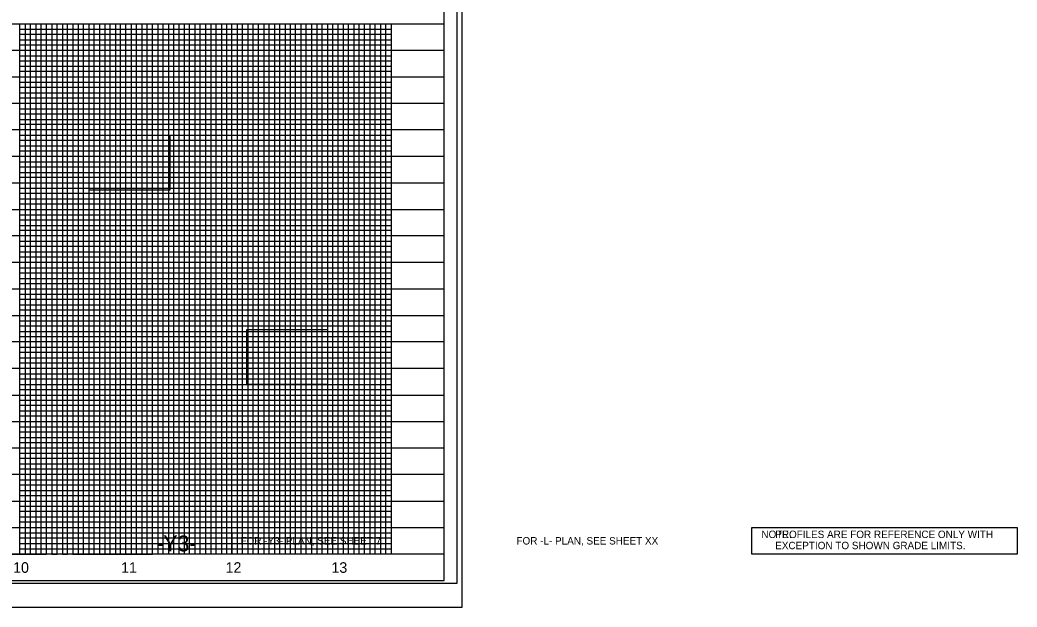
# Model space of a CAD drawing. Extents: x 1629737 to 1631945, y 1172886 to 1173986.
# Drawn here: x 1631004 to 1631945, y 1172886 to 1173440 of the extents above; entities that cross this region are included whole.
import ezdxf

# ---------------------------------------------------------------- set-up
doc = ezdxf.new("R2010")
doc.units = 0
for name, color, linetype in [('Exist Vertical Profile Horizontal Axis Label Major', 7, 'Continuous'), ('Prop Dimension Text', 7, 'Continuous'), ('Prop Grid Mask', 7, 'Continuous'), ('Sheet Data Field CELL', 7, 'Continuous'), ('Sheet Layout Profile Border Port 2', 7, 'Continuous'), ('Sheet Plot Border Inside CELL', 7, 'Continuous'), ('Sheet Plot Border Outside CELL', 7, 'Continuous'), ('Sheet Profile CELL', 7, 'Continuous'), ('Sheet Profile Grid Major CELL', 7, 'Continuous'), ('Sheet Profile Grid Middle CELL', 7, 'Continuous'), ('Sheet Profile Grid Minor CELL', 7, 'Continuous')]:
    doc.layers.add(name, color=color, linetype=linetype)

msp = doc.modelspace()

# ---------------------------------------------------------------- linework, layer by layer
at = {"layer": 'Prop Grid Mask'}
for points in [[(1631069.74, 1173330.94), (1631145.61, 1173330.94), (1631145.61, 1173279.17), (1631069.74, 1173279.17)], [(1631218.44, 1173147.7), (1631294.31, 1173147.7), (1631294.31, 1173095.94), (1631218.44, 1173095.94)], [(1631104.31, 1172955.94), (1631204.31, 1172955.94), (1631204.31, 1172935.94), (1631104.31, 1172935.94)], [(1631204.31, 1172960.94), (1631354.31, 1172960.94), (1631354.31, 1172935.94), (1631204.31, 1172935.94)]]:
    msp.add_lwpolyline(points, close=True, dxfattribs=at)
at = {"layer": 'Sheet Data Field CELL'}
msp.add_lwpolyline([(1631944.74, 1172935.94), (1631694.74, 1172935.94), (1631694.74, 1172960.94), (1631944.74, 1172960.94)], close=True, dxfattribs=at)
at = {"layer": 'Sheet Layout Profile Border Port 2'}
msp.add_lwpolyline([(1631004.31, 1173435.94), (1631354.31, 1173435.94), (1631354.31, 1172935.94), (1631204.31, 1172935.94), (1631129.31, 1172935.94), (1631004.31, 1172935.94)], close=True, dxfattribs=at)
at = {"layer": 'Sheet Plot Border Inside CELL'}
msp.add_lwpolyline([(1629750.31, 1172908.39), (1631416.81, 1172908.39), (1631416.81, 1173963.49), (1629750.31, 1173963.49)], close=True, dxfattribs=at)
at = {"layer": 'Sheet Plot Border Outside CELL'}
msp.add_lwpolyline([(1629737.31, 1172885.94), (1631421.31, 1172885.94), (1631421.31, 1173985.94), (1629737.31, 1173985.94)], close=True, dxfattribs=at)
at = {"layer": 'Sheet Profile CELL'}
for p, q in [((1629904.31, 1173435.94), (1631404.31, 1173435.94)), ((1631404.31, 1172935.94), (1629904.31, 1172935.94)), ((1629904.31, 1172910.94), (1631404.31, 1172910.94))]:
    msp.add_line(p, q, dxfattribs=at)
msp.add_lwpolyline([(1631404.31, 1173960.94), (1629904.31, 1173960.94), (1629904.31, 1172910.94), (1631404.31, 1172910.94)], close=True, dxfattribs=at)
at = {"layer": 'Sheet Profile Grid Major CELL'}
for p, q in [((1631004.31, 1173435.94), (1631054.31, 1173435.94)), ((1631004.31, 1172935.94), (1631004.31, 1173435.94)), ((1631004.31, 1173435.94), (1631054.31, 1173435.94)), ((1631054.31, 1173435.94), (1631054.31, 1172935.94)), ((1631104.31, 1173435.94), (1631154.31, 1173435.94)), ((1631104.31, 1172935.94), (1631104.31, 1173435.94)), ((1631104.31, 1173435.94), (1631154.31, 1173435.94)), ((1631154.31, 1173435.94), (1631154.31, 1172935.94)), ((1631204.31, 1173435.94), (1631254.31, 1173435.94)), ((1631304.31, 1173435.94), (1631354.31, 1173435.94)), ((1631304.31, 1173435.94), (1631354.31, 1173435.94)), ((1631304.31, 1172935.94), (1631304.31, 1173435.94)), ((1631354.31, 1173435.94), (1631354.31, 1172935.94)), ((1630954.31, 1172935.94), (1631004.31, 1172935.94)), ((1631054.31, 1172935.94), (1631104.31, 1172935.94))]:
    msp.add_line(p, q, dxfattribs=at)
for points in [[(1631204.31, 1172935.94), (1631204.31, 1173435.94), (1631254.31, 1173435.94), (1631254.31, 1172935.94)], [(1631404.31, 1173410.94), (1629904.31, 1173410.94)], [(1631404.31, 1173360.94), (1629904.31, 1173360.94)], [(1631404.31, 1173310.94), (1629904.31, 1173310.94), (1629904.31, 1173260.94), (1631404.31, 1173260.94)], [(1631404.31, 1173210.94), (1629904.31, 1173210.94), (1629904.31, 1173160.94), (1631404.31, 1173160.94)], [(1631404.31, 1173110.94), (1629904.31, 1173110.94), (1629904.31, 1173060.94), (1631404.31, 1173060.94)], [(1631404.31, 1173010.94), (1629904.31, 1173010.94), (1629904.31, 1173010.94), (1629904.31, 1172960.94), (1631404.31, 1172960.94)], [(1631404.31, 1172935.94), (1629904.31, 1172935.94)]]:
    msp.add_lwpolyline(points, dxfattribs=at)
at = {"layer": 'Sheet Profile Grid Middle CELL'}
for p, q in [((1631029.31, 1172935.94), (1631029.31, 1173435.94)), ((1631029.31, 1173435.94), (1631079.31, 1173435.94)), ((1631079.31, 1173435.94), (1631079.31, 1172935.94)), ((1630979.31, 1172935.94), (1631029.31, 1172935.94)), ((1631079.31, 1172935.94), (1631129.31, 1172935.94))]:
    msp.add_line(p, q, dxfattribs=at)
for points in [[(1631129.31, 1172935.94), (1631129.31, 1173435.94), (1631179.31, 1173435.94), (1631179.31, 1172935.94)], [(1631229.31, 1172935.94), (1631229.31, 1173435.94), (1631279.31, 1173435.94), (1631279.31, 1172935.94)], [(1631329.31, 1172935.94), (1631329.31, 1173435.94)], [(1629904.31, 1173385.94), (1631404.31, 1173385.94)], [(1631404.31, 1173335.94), (1629904.31, 1173335.94), (1629904.31, 1173285.94), (1631404.31, 1173285.94)], [(1631404.31, 1173235.94), (1629904.31, 1173235.94), (1629904.31, 1173185.94), (1631404.31, 1173185.94)], [(1631404.31, 1173135.94), (1629904.31, 1173135.94), (1629904.31, 1173085.94), (1631404.31, 1173085.94)], [(1631404.31, 1173035.94), (1629904.31, 1173035.94), (1629904.31, 1172985.94), (1631404.31, 1172985.94)], [(1631404.31, 1172935.94), (1629904.31, 1172935.94)]]:
    msp.add_lwpolyline(points, dxfattribs=at)
at = {"layer": 'Sheet Profile Grid Minor CELL'}
for p, q in [((1630999.31, 1173435.94), (1631009.31, 1173435.94)), ((1631009.31, 1173435.94), (1631009.31, 1172935.94)), ((1631014.31, 1172935.94), (1631014.31, 1173435.94)), ((1631014.31, 1173435.94), (1631019.31, 1173435.94)), ((1631019.31, 1173435.94), (1631019.31, 1172935.94)), ((1631024.31, 1172935.94), (1631024.31, 1173435.94)), ((1631024.31, 1173435.94), (1631034.31, 1173435.94)), ((1631034.31, 1173435.94), (1631034.31, 1172935.94)), ((1631039.31, 1172935.94), (1631039.31, 1173435.94)), ((1631039.31, 1173435.94), (1631044.31, 1173435.94)), ((1631044.31, 1173435.94), (1631044.31, 1172935.94)), ((1631049.31, 1172935.94), (1631049.31, 1173435.94)), ((1631049.31, 1173435.94), (1631059.31, 1173435.94)), ((1631059.31, 1173435.94), (1631059.31, 1172935.94)), ((1631064.31, 1172935.94), (1631064.31, 1173435.94)), ((1631064.31, 1173435.94), (1631069.31, 1173435.94)), ((1631069.31, 1173435.94), (1631069.31, 1172935.94)), ((1631074.31, 1172935.94), (1631074.31, 1173435.94)), ((1631074.31, 1173435.94), (1631084.31, 1173435.94)), ((1631084.31, 1173435.94), (1631084.31, 1172935.94)), ((1631089.31, 1172935.94), (1631089.31, 1173435.94)), ((1631089.31, 1173435.94), (1631094.31, 1173435.94)), ((1631094.31, 1173435.94), (1631094.31, 1172935.94)), ((1631004.31, 1173430.94), (1631354.31, 1173430.94)), ((1631354.31, 1173425.94), (1631004.31, 1173425.94)), ((1631004.31, 1173420.94), (1631354.31, 1173420.94)), ((1631354.31, 1173415.94), (1631004.31, 1173415.94)), ((1631004.31, 1173405.94), (1631354.31, 1173405.94)), ((1631354.31, 1173400.94), (1631004.31, 1173400.94)), ((1631004.31, 1173395.94), (1631354.31, 1173395.94)), ((1631354.31, 1173390.94), (1631004.31, 1173390.94)), ((1631004.31, 1173380.94), (1631354.31, 1173380.94)), ((1631354.31, 1173375.94), (1631004.31, 1173375.94)), ((1631004.31, 1173370.94), (1631354.31, 1173370.94)), ((1631354.31, 1173365.94), (1631004.31, 1173365.94)), ((1631004.31, 1173355.94), (1631354.31, 1173355.94)), ((1631354.31, 1173350.94), (1631004.31, 1173350.94)), ((1631004.31, 1173345.94), (1631354.31, 1173345.94)), ((1631354.31, 1173340.94), (1631004.31, 1173340.94)), ((1631004.31, 1173330.94), (1631354.31, 1173330.94)), ((1631354.31, 1173325.94), (1631004.31, 1173325.94)), ((1631004.31, 1173320.94), (1631354.31, 1173320.94)), ((1631354.31, 1173315.94), (1631004.31, 1173315.94)), ((1631004.31, 1173305.94), (1631354.31, 1173305.94)), ((1631354.31, 1173300.94), (1631004.31, 1173300.94)), ((1631004.31, 1173295.94), (1631354.31, 1173295.94)), ((1631354.31, 1173290.94), (1631004.31, 1173290.94)), ((1631004.31, 1173280.94), (1631354.31, 1173280.94)), ((1631354.31, 1173275.94), (1631004.31, 1173275.94)), ((1631004.31, 1173270.94), (1631354.31, 1173270.94)), ((1631354.31, 1173265.94), (1631004.31, 1173265.94)), ((1631004.31, 1173255.94), (1631354.31, 1173255.94)), ((1631354.31, 1173250.94), (1631004.31, 1173250.94)), ((1631004.31, 1173245.94), (1631354.31, 1173245.94)), ((1631354.31, 1173240.94), (1631004.31, 1173240.98)), ((1631004.31, 1173230.94), (1631354.31, 1173230.94)), ((1631354.31, 1173225.94), (1631004.31, 1173225.94)), ((1631004.31, 1173220.94), (1631354.31, 1173220.94)), ((1631354.31, 1173215.94), (1631004.31, 1173215.94)), ((1631004.31, 1173205.94), (1631354.31, 1173205.94)), ((1631354.31, 1173200.94), (1631004.31, 1173200.94)), ((1631004.31, 1173195.94), (1631354.31, 1173195.94)), ((1631354.31, 1173190.94), (1631004.31, 1173190.94)), ((1631004.31, 1173180.94), (1631354.31, 1173180.94)), ((1631354.31, 1173175.94), (1631004.31, 1173175.94)), ((1631004.31, 1173170.94), (1631354.31, 1173170.94)), ((1631354.31, 1173165.94), (1631004.31, 1173165.94)), ((1631004.31, 1173155.94), (1631354.31, 1173155.94)), ((1631354.31, 1173150.94), (1631004.31, 1173150.94)), ((1631004.31, 1173145.94), (1631354.31, 1173145.94)), ((1631354.31, 1173140.94), (1631004.31, 1173140.94)), ((1631004.31, 1173130.94), (1631354.31, 1173130.94)), ((1631354.31, 1173125.94), (1631004.31, 1173125.94)), ((1631004.31, 1173120.94), (1631354.31, 1173120.94)), ((1631354.31, 1173115.94), (1631004.31, 1173115.94)), ((1631004.31, 1173105.94), (1631354.31, 1173105.94)), ((1631354.31, 1173100.94), (1631004.31, 1173100.94)), ((1631004.31, 1173095.94), (1631354.31, 1173095.94)), ((1631354.31, 1173090.94), (1631004.31, 1173090.94)), ((1631004.31, 1173080.94), (1631354.31, 1173080.94)), ((1631354.31, 1173075.94), (1631004.31, 1173075.94)), ((1631004.31, 1173070.94), (1631354.31, 1173070.94)), ((1631354.31, 1173065.94), (1631004.31, 1173065.94)), ((1631004.31, 1173055.94), (1631354.31, 1173055.94)), ((1631354.31, 1173050.94), (1631004.31, 1173050.94)), ((1631004.31, 1173045.94), (1631354.31, 1173045.94)), ((1631354.31, 1173040.94), (1631004.31, 1173040.94)), ((1631004.31, 1173030.94), (1631354.31, 1173030.94)), ((1631354.31, 1173025.94), (1631004.31, 1173025.94)), ((1631004.31, 1173020.94), (1631354.31, 1173020.94)), ((1631354.31, 1173015.94), (1631004.31, 1173015.94)), ((1631004.31, 1173005.94), (1631354.31, 1173005.94)), ((1631354.31, 1173000.94), (1631004.31, 1173000.94)), ((1631004.31, 1172995.94), (1631354.31, 1172995.94)), ((1631354.31, 1172990.94), (1631004.31, 1172990.94)), ((1631004.31, 1172980.94), (1631354.31, 1172980.94)), ((1631354.31, 1172975.94), (1631004.31, 1172975.94)), ((1631004.31, 1172970.94), (1631354.31, 1172970.94)), ((1631354.31, 1172965.94), (1631004.31, 1172965.94)), ((1631004.31, 1172955.94), (1631354.31, 1172955.94)), ((1631354.31, 1172950.94), (1631004.31, 1172950.94)), ((1631004.31, 1172945.94), (1631354.31, 1172945.94)), ((1631004.31, 1172940.94), (1631354.31, 1172940.94)), ((1631009.31, 1172935.94), (1631014.31, 1172935.94)), ((1631019.31, 1172935.94), (1631024.31, 1172935.94)), ((1631034.31, 1172935.94), (1631039.31, 1172935.94)), ((1631044.31, 1172935.94), (1631049.31, 1172935.94)), ((1631059.31, 1172935.94), (1631064.31, 1172935.94)), ((1631069.31, 1172935.94), (1631074.31, 1172935.94)), ((1631084.31, 1172935.94), (1631089.31, 1172935.94))]:
    msp.add_line(p, q, dxfattribs=at)
for points in [[(1631094.31, 1172935.94), (1631099.31, 1172935.94), (1631099.31, 1173435.94), (1631109.31, 1173435.94), (1631109.31, 1172935.94)], [(1631114.31, 1172935.94), (1631114.31, 1173435.94), (1631119.31, 1173435.94), (1631119.31, 1172935.94)], [(1631124.31, 1172935.94), (1631124.31, 1173435.94), (1631134.31, 1173435.94), (1631134.31, 1172935.94)], [(1631139.31, 1172935.94), (1631139.31, 1173435.94), (1631144.31, 1173435.94), (1631144.31, 1172935.94)], [(1631149.31, 1172935.94), (1631149.31, 1173435.94), (1631159.31, 1173435.94), (1631159.31, 1172935.94)], [(1631164.31, 1172935.94), (1631164.31, 1173435.94), (1631169.31, 1173435.94), (1631169.31, 1172935.94)], [(1631174.31, 1172935.94), (1631174.31, 1173435.94), (1631184.31, 1173435.94), (1631184.31, 1172935.94)], [(1631189.31, 1172935.94), (1631189.31, 1173435.94), (1631194.31, 1173435.94), (1631194.31, 1172935.94)], [(1631199.31, 1172935.94), (1631199.31, 1173435.94), (1631209.31, 1173435.94), (1631209.31, 1172935.94)], [(1631214.31, 1172935.94), (1631214.31, 1173435.94), (1631219.31, 1173435.94), (1631219.31, 1172935.94)], [(1631224.31, 1172935.94), (1631224.31, 1173435.94), (1631234.31, 1173435.94), (1631234.31, 1172935.94)], [(1631239.31, 1172935.94), (1631239.31, 1173435.94), (1631244.31, 1173435.94), (1631244.31, 1172935.94)], [(1631249.31, 1172935.94), (1631249.31, 1173435.94), (1631259.31, 1173435.94), (1631259.31, 1172935.94)], [(1631264.31, 1172935.94), (1631264.31, 1173435.94), (1631269.31, 1173435.94), (1631269.31, 1172935.94)], [(1631274.31, 1172935.94), (1631274.31, 1173435.94), (1631284.31, 1173435.94), (1631284.31, 1172935.94)], [(1631289.31, 1172935.94), (1631289.31, 1173435.94), (1631294.31, 1173435.94), (1631294.31, 1172935.94)], [(1631299.31, 1172935.94), (1631299.31, 1173435.94), (1631309.31, 1173435.94), (1631309.31, 1172935.94)], [(1631314.31, 1172935.94), (1631314.31, 1173435.94), (1631319.31, 1173435.94), (1631319.31, 1172935.94)], [(1631324.31, 1172935.94), (1631324.31, 1173435.94), (1631334.31, 1173435.94), (1631334.31, 1172935.94)], [(1631339.31, 1172935.94), (1631339.31, 1173435.94), (1631344.31, 1173435.94), (1631344.31, 1172935.94)], [(1631349.31, 1172935.94), (1631349.31, 1173435.94), (1631354.31, 1173435.94)]]:
    msp.add_lwpolyline(points, dxfattribs=at)

# ---------------------------------------------------------------- texts
at = {"layer": 'Exist Vertical Profile Horizontal Axis Label Major'}
for s, p in [('10', (1630997.9, 1172918.23)), ('11', (1631099.74, 1172918.23)), ('12', (1631198.29, 1172918.23)), ('13', (1631298.12, 1172918.23))]:
    msp.add_text(s, height=10, dxfattribs=at).set_placement(p)
at = {"layer": 'Prop Dimension Text'}
msp.add_text('FOR -L- PLAN, SEE SHEET XX', height=7, rotation=360, dxfattribs=at).set_placement((1631472.6, 1172944.94))
at = {"layer": 'Sheet Data Field CELL'}
for s, p in [('NOTE: ', (1631703.64, 1172951.02)), ('     PROFILES ARE FOR REFERENCE ONLY WITH', (1631703.64, 1172951.02)), ('     EXCEPTION TO SHOWN GRADE LIMITS.', (1631703.64, 1172940.52))]:
    msp.add_text(s, height=7, dxfattribs=at).set_placement(p)
for s, height, p in [('-Y3-', 15, (1631132.88, 1172938.44)), ('FOR -Y3- PLAN, SEE SHEET 7', 7, (1631212.38, 1172944.94))]:
    msp.add_text(s, height=height, rotation=360, dxfattribs=at).set_placement(p)

doc.saveas('drawing.dxf')
